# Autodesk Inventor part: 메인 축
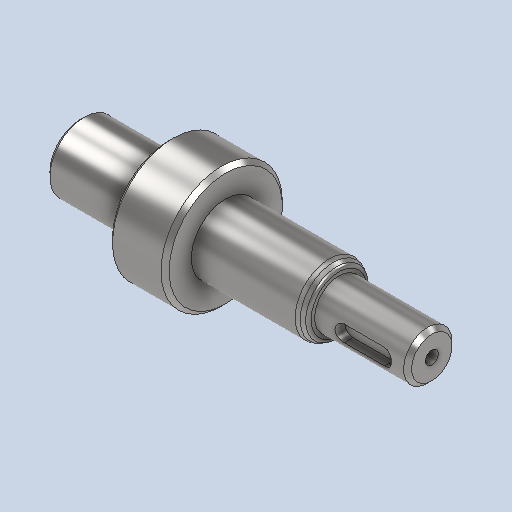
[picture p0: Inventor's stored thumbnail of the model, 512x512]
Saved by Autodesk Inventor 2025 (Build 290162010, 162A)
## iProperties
Created: 2024-07
Part Number: 메인 축
Material: 강철, 연강
Document SubType Name: Modeling
Designer: Admin
Density: 7.86 g/cm^3
Appearance: 기본값
Author: jhkim
Revision Number: 1
Sending System: Autodesk Inventor 2025
Preprocessor: ST-DEVELOPER v20
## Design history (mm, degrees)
feature "솔리드1"
node "솔리드2"
